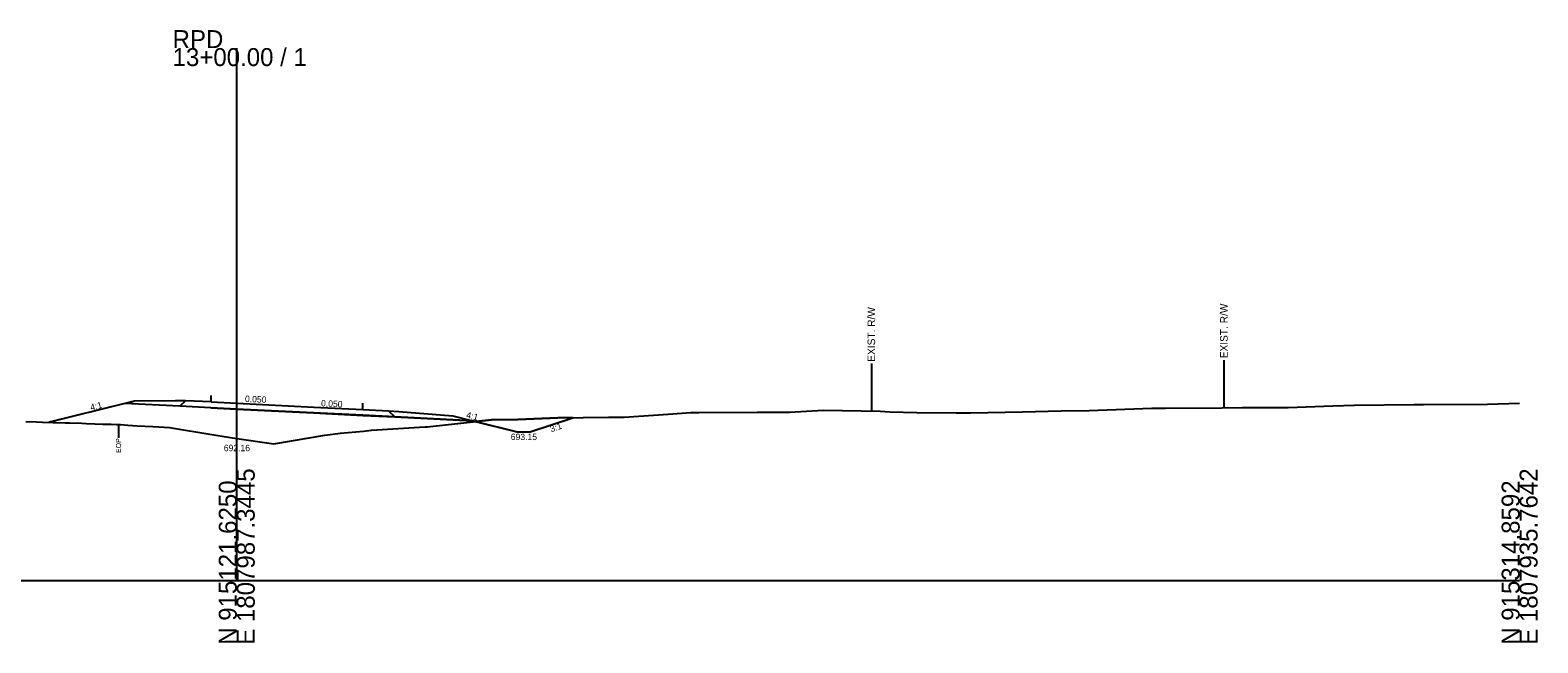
# Model space of a CAD drawing. Extents: x -26 to 403, y -10 to 8517.
# Drawn here: x 167.8 to 402.8, y 5990.3 to 6085.7 of the extents above; entities that cross this region are included whole.
import ezdxf

# ---------------------------------------------------------------- set-up
doc = ezdxf.new("R2010")
doc.units = 0
for name, color, linetype in [('Exist Cross Section Cell', 7, 'Continuous'), ('Exist XS Center Line Elevation Label', 7, 'Continuous'), ('Exist XS Ground Line', 7, 'Continuous'), ('Old_Level_10', 7, 'Continuous'), ('Prop XS Ditch Slope Text', 7, 'Continuous'), ('Prop XS Ditch Standard Text', 7, 'Continuous'), ('Prop XS Earthwork Shape', 7, 'Continuous'), ('Prop XS EOT Tick Mark', 7, 'Continuous'), ('Prop XS Finish Grade', 7, 'Continuous'), ('Prop XS Finish Grade Earthwork', 7, 'Continuous'), ('Prop XS Finish Grade Paved Shoulder', 7, 'Continuous'), ('Prop XS Finish Grade Pavement', 7, 'Continuous'), ('Prop XS Hydro Fill Slope Data', 7, 'Continuous'), ('Prop XS Pvmt Edge Slope', 7, 'Continuous'), ('Prop XS SE Text', 7, 'Continuous'), ('Prop XS Side Slope Text', 7, 'Continuous'), ('Prop XS Subgrade Earthwork', 7, 'Continuous')]:
    doc.layers.add(name, color=color, linetype=linetype)

msp = doc.modelspace()

# ---------------------------------------------------------------- linework, layer by layer
at = {"layer": 'Exist Cross Section Cell'}
for p, q in [((200, 6000), (200, 6082.95)), ((0, 6000), (200, 6000)), ((200, 6000), (400, 6000))]:
    msp.add_line(p, q, dxfattribs=at)
at = {"layer": 'Exist XS Ground Line'}
msp.add_lwpolyline([(167.09, 6024.76), (168.78, 6024.72), (169.73, 6024.69), (171.36, 6024.64), (171.77, 6024.63), (173.31, 6024.58), (173.95, 6024.57), (175.86, 6024.5), (176.53, 6024.48), (177.89, 6024.43), (179.12, 6024.39), (180.42, 6024.35), (181.22, 6024.32), (181.56, 6024.31), (181.88, 6024.3), (183.02, 6024.22), (184.48, 6024.12), (186.93, 6024), (187.87, 6023.93), (189.49, 6023.84), (196.4, 6022.7), (200, 6022.16), (205.77, 6021.3), (213.72, 6022.65), (216.17, 6022.98), (219.75, 6023.28), (221.01, 6023.46), (228.48, 6023.89), (229.37, 6023.95), (229.69, 6023.97), (239.72, 6025.02), (243.81, 6025.12), (250.07, 6025.34), (257.93, 6025.45), (260.42, 6025.46), (267.25, 6025.95), (270.77, 6026.2), (272.05, 6026.21), (281.12, 6026.23), (286.17, 6026.25), (291.47, 6026.57), (300.29, 6026.37), (301.82, 6026.3), (306.03, 6026.18), (312.17, 6026.14), (314.41, 6026.15), (322.52, 6026.28), (328.53, 6026.45), (332.87, 6026.51), (342.64, 6026.85), (343.22, 6026.86), (344.8, 6026.88), (353.57, 6026.93), (356.76, 6026.96), (363.92, 6026.96), (370.88, 6027.22), (374.27, 6027.32), (383.58, 6027.43), (384.62, 6027.43), (385, 6027.44), (394.97, 6027.47), (400, 6027.65)], dxfattribs=at)
at = {"layer": 'Old_Level_10'}
for p, q in [((298.93, 6033.8), (298.93, 6026.4)), ((353.9, 6034.34), (353.9, 6026.94)), ((181.56, 6024.31), (181.56, 6022.26))]:
    msp.add_line(p, q, dxfattribs=at)
at = {"layer": 'Prop XS Earthwork Shape'}
for points in [[(179.12, 6024.39), (180.42, 6024.35), (181.22, 6024.32), (181.56, 6024.31), (181.88, 6024.3), (183.02, 6024.22), (184.48, 6024.12), (186.93, 6024), (187.87, 6023.93), (189.49, 6023.84), (196.4, 6022.7), (200, 6022.16), (205.77, 6021.3), (213.72, 6022.65), (216.17, 6022.98), (219.75, 6023.28), (221.01, 6023.46), (228.48, 6023.89), (229.37, 6023.95), (229.69, 6023.97), (237.29, 6024.76), (236.74, 6024.9), (224.63, 6025.51), (219.64, 6025.75), (211.98, 6026.14), (199.98, 6026.73), (195.98, 6026.93), (191.13, 6027.17), (182.54, 6027.6), (170.77, 6024.66), (171.36, 6024.64), (171.77, 6024.63), (173.31, 6024.58), (173.95, 6024.57), (175.86, 6024.5), (176.53, 6024.48), (177.89, 6024.43)], [(237.29, 6024.76), (243.75, 6023.15), (245.75, 6023.15), (252.41, 6025.37), (250.07, 6025.34), (243.81, 6025.12), (239.72, 6025.02)], [(245.75, 6023.15), (252.41, 6025.37), (250.07, 6025.34), (243.81, 6025.12), (239.72, 6025.02), (237.29, 6024.76), (243.75, 6023.15)]]:
    msp.add_lwpolyline(points, close=True, dxfattribs=at)
at = {"layer": 'Prop XS EOT Tick Mark'}
for p, q in [((196, 6027.83), (196, 6028.83)), ((219.66, 6026.65), (219.66, 6027.65))]:
    msp.add_line(p, q, dxfattribs=at)
at = {"layer": 'Prop XS Finish Grade'}
for p, q in [((182.54, 6027.58), (184, 6027.95)), ((190.43, 6028.01), (184, 6027.95)), ((192, 6028.03), (190.43, 6028.01)), ((223.66, 6026.45), (225.29, 6026.32)), ((225.29, 6026.32), (233.66, 6025.65)), ((233.66, 6025.65), (236.74, 6024.88))]:
    msp.add_line(p, q, dxfattribs=at)
at = {"layer": 'Prop XS Finish Grade Earthwork'}
for p, q in [((182.54, 6027.58), (170.85, 6024.66)), ((236.74, 6024.88), (243.67, 6023.15)), ((245.67, 6023.15), (252.33, 6025.37)), ((243.67, 6023.15), (245.67, 6023.15))]:
    msp.add_line(p, q, dxfattribs=at)
at = {"layer": 'Prop XS Finish Grade Paved Shoulder'}
for p, q in [((196, 6027.83), (192, 6028.03)), ((219.66, 6026.65), (223.66, 6026.45))]:
    msp.add_line(p, q, dxfattribs=at)
at = {"layer": 'Prop XS Finish Grade Pavement'}
for p, q in [((196, 6027.83), (200, 6027.63)), ((200, 6027.63), (212, 6027.03)), ((212, 6027.03), (219.66, 6026.65))]:
    msp.add_line(p, q, dxfattribs=at)
at = {"layer": 'Prop XS Hydro Fill Slope Data'}
msp.add_line((184, 6027.95), (170.85, 6024.66), dxfattribs=at)
at = {"layer": 'Prop XS Pvmt Edge Slope'}
for p, q in [((192, 6028.03), (191.13, 6027.15)), ((223.66, 6026.45), (224.63, 6025.49))]:
    msp.add_line(p, q, dxfattribs=at)
at = {"layer": 'Prop XS Subgrade Earthwork'}
for p, q in [((191.13, 6027.15), (182.54, 6027.58)), ((195.98, 6026.91), (191.13, 6027.15)), ((195.98, 6026.91), (199.98, 6026.71)), ((199.98, 6026.71), (211.98, 6026.12)), ((211.98, 6026.12), (219.64, 6025.73)), ((219.64, 6025.73), (224.63, 6025.49)), ((224.63, 6025.49), (236.74, 6024.88))]:
    msp.add_line(p, q, dxfattribs=at)

# ---------------------------------------------------------------- texts
at = {"layer": 'Exist Cross Section Cell'}
for s, p in [('RPD', (190, 6082.95)), ('13+00.00 / 1', (190, 6080.15))]:
    msp.add_text(s, height=2.8, dxfattribs=at).set_placement(p)
for s, p in [('E 1807987.3445', (202.8, 5990)), ('E 1807935.7642', (402.8, 5990)), ('N 915121.6250', (200, 5990)), ('N 915314.8592', (400, 5990))]:
    msp.add_text(s, height=2.8, rotation=90, dxfattribs=at).set_placement(p)
at = {"layer": 'Exist XS Center Line Elevation Label'}
msp.add_text('692.16', height=1, dxfattribs=at).set_placement((197.98, 6020.16))
at = {"layer": 'Old_Level_10'}
for s, height, rotation, p in [('EXIST. R/W', 1.181, 90, (354.49, 6034.64)), ('EXIST. R/W', 1.181, 90, (299.52, 6034.1)), ('3:1', 1, 18.4349, (249.02, 6023.1)), ('EOP', 0.787, 90, (181.95, 6019.87))]:
    msp.add_text(s, height=height, rotation=rotation, dxfattribs=at).set_placement(p)
at = {"layer": 'Prop XS Ditch Slope Text'}
msp.add_text('4:1', height=1, rotation=345.9638, dxfattribs=at).set_placement((235.7, 6025.37))
at = {"layer": 'Prop XS Ditch Standard Text'}
msp.add_text('693.15', height=1, dxfattribs=at).set_placement((242.72, 6021.89))
at = {"layer": 'Prop XS SE Text'}
for p in [(201.26, 6027.84), (213.12, 6027.14)]:
    msp.add_text('0.050', height=1, rotation=357.1487, dxfattribs=at).set_placement(p)
at = {"layer": 'Prop XS Side Slope Text'}
msp.add_text('4:1', height=1, rotation=14.0362, dxfattribs=at).set_placement((177.29, 6026.47))

doc.saveas('drawing.dxf')
